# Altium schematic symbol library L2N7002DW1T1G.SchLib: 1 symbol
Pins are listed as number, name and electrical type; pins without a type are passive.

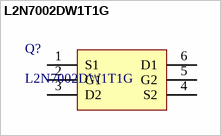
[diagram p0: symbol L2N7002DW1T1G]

## L2N7002DW1T1G
designator Q?
footprint SOT-363
pins: 1 S1, 2 G1, 3 D2, 4 S2, 5 G2, 6 D1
